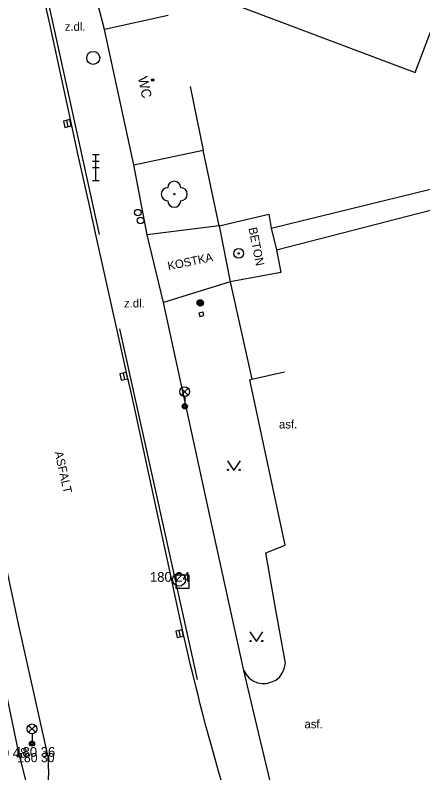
# Model space of a CAD drawing. Extents: x -538441 to -536770, y -1181008 to -1179809.
# Drawn here: x -537773.6 to -537742.3, y -1180678.1 to -1180620 of the extents above; entities that cross this region are included whole.
import ezdxf

# ---------------------------------------------------------------- set-up
doc = ezdxf.new("R2010")
doc.units = 0
for name, color, linetype in [('Vrstva 10', 7, 'Continuous'), ('Vrstva 11', 7, 'Continuous'), ('Vrstva 21', 7, 'Continuous'), ('Vrstva 22', 7, 'Continuous'), ('Vrstva 24', 7, 'Continuous'), ('Vrstva 25', 7, 'Continuous'), ('Vrstva 26', 7, 'Continuous'), ('Vrstva 27', 7, 'Continuous'), ('Vrstva 28', 7, 'Continuous'), ('Vrstva 30', 7, 'Continuous'), ('Vrstva 33', 7, 'Continuous'), ('Vrstva 36', 7, 'Continuous'), ('Vrstva 39', 7, 'Continuous'), ('Vrstva 4', 7, 'Continuous'), ('Vrstva 40', 7, 'Continuous'), ('Vrstva 41', 7, 'Continuous'), ('Vrstva 5', 7, 'Continuous'), ('Vrstva 7', 7, 'Continuous'), ('Vrstva 8', 7, 'Continuous'), ('Vrstva 9', 7, 'Continuous')]:
    doc.layers.add(name, color=color, linetype=linetype)

msp = doc.modelspace()

# ---------------------------------------------------------------- linework, layer by layer
at = {"layer": 'Vrstva 10'}
for p, q in [((-537770.915, -1180620.685), (-537772.621, -1180613.186)), ((-537769.28, -1180628.26), (-537770.915, -1180620.685)), ((-537765.509, -1180645.218), (-537767.41, -1180636.742)), ((-537764.97, -1180647.64), (-537765.509, -1180645.218)), ((-537775.93, -1180654.62), (-537773.33, -1180666.81)), ((-537761.688, -1180662.769), (-537763.319, -1180655.202)), ((-537761.219, -1180664.93), (-537761.688, -1180662.769))]:
    msp.add_line(p, q, dxfattribs=at)
for points in [[(-537767.41, -1180636.742), (-537767.883, -1180634.623), (-537768.236, -1180633.033), (-537768.761, -1180630.647), (-537769.28, -1180628.26)], [(-537763.319, -1180655.202), (-537763.728, -1180653.311), (-537764.346, -1180650.475), (-537764.657, -1180649.057), (-537764.97, -1180647.64)], [(-537758.935, -1180674.513), (-537759.17, -1180673.628), (-537759.372, -1180672.853), (-537759.546, -1180672.174), (-537759.696, -1180671.579), (-537759.953, -1180670.538), (-537760.141, -1180669.755), (-537760.28, -1180669.167), (-537760.483, -1180668.284), (-537760.68, -1180667.4), (-537761.219, -1180664.93)], [(-537773.33, -1180666.81), (-537772.713, -1180669.563)], [(-537772.713, -1180669.563), (-537771.07, -1180676.89)], [(-537756.199, -1180683.987), (-537756.511, -1180682.957), (-537756.801, -1180681.991), (-537757.071, -1180681.086), (-537757.322, -1180680.236), (-537757.554, -1180679.439), (-537757.771, -1180678.692), (-537757.972, -1180677.991), (-537758.343, -1180676.675), (-537758.662, -1180675.522), (-537758.935, -1180674.513)], [(-537771.07, -1180676.89), (-537771.02, -1180678.163), (-537771.13, -1180679.42), (-537771.4, -1180680.668), (-537771.823, -1180681.866), (-537771.94, -1180682.13)]]:
    msp.add_lwpolyline(points, dxfattribs=at)
at = {"layer": 'Vrstva 11'}
for p, q in [((-537757.908, -1180618.739), (-537742.89, -1180624.41)), ((-537742.89, -1180624.41), (-537740.772, -1180618.801)), ((-537763.452, -1180636.853), (-537764.47, -1180631.49)), ((-537753.53, -1180638.01), (-537734.2, -1180633.02)), ((-537757.93, -1180636.17), (-537754.12, -1180635.28)), ((-537754.12, -1180635.28), (-537753.93, -1180636.35)), ((-537757.93, -1180636.17), (-537763.452, -1180636.853)), ((-537753.93, -1180636.35), (-537753.53, -1180638.01)), ((-537762.187, -1180642.047), (-537763.452, -1180636.853)), ((-537753.53, -1180638.01), (-537753.2, -1180639.76)), ((-537753.2, -1180639.76), (-537757.07, -1180640.46)), ((-537757.07, -1180640.46), (-537762.187, -1180642.047)), ((-537758.607, -1180658.503), (-537762.187, -1180642.047)), ((-537755.574, -1180647.981), (-537755.408, -1180647.932)), ((-537752.87, -1180660.656), (-537755.574, -1180647.981)), ((-537756.028, -1180670.259), (-537758.607, -1180658.503)), ((-537754.35, -1180661.261), (-537752.87, -1180660.656)), ((-537773.21, -1180676.96), (-537774.66, -1180670.06)), ((-537754.899, -1180675.016), (-537756.028, -1180670.259)), ((-537753.677, -1180680.146), (-537754.899, -1180675.016)), ((-537773.21, -1180676.96), (-537771.94, -1180682.13))]:
    msp.add_line(p, q, dxfattribs=at)
for points in [[(-537766.73, -1180621.12), (-537767.266, -1180619.04), (-537767.504, -1180617.426), (-537768.734, -1180617.736), (-537769.132, -1180616.088), (-537767.464, -1180615.743)], [(-537753.93, -1180636.35), (-537735.558, -1180631.868)], [(-537752.846, -1180669.719), (-537753.593, -1180665.498), (-537754.35, -1180661.261)], [(-537756.028, -1180670.259), (-537755.852, -1180670.577), (-537755.611, -1180670.849), (-537755.316, -1180671.062), (-537754.982, -1180671.205), (-537754.625, -1180671.273), (-537754.262, -1180671.26), (-537753.95, -1180671.16), (-537753.587, -1180671.003), (-537753.307, -1180670.771), (-537753.085, -1180670.483), (-537752.931, -1180670.154), (-537752.853, -1180669.799), (-537752.846, -1180669.719)]]:
    msp.add_lwpolyline(points, dxfattribs=at)
at = {"layer": 'Vrstva 21'}
for radius in [0.375, 0.05]:
    msp.add_circle((-537756.42, -1180638.29), radius, dxfattribs=at)
at = {"layer": 'Vrstva 22'}
msp.add_circle((-537761.37, -1180633.75), 0.05, dxfattribs=at)
for centre, start, end in [((-537761.37, -1180633.25), 0, 180), ((-537761.87, -1180633.75), 90, 270), ((-537760.87, -1180633.75), 270, 90), ((-537761.37, -1180634.25), 180, 0)]:
    msp.add_arc(centre, 0.5, start, end, dxfattribs=at)
at = {"layer": 'Vrstva 24'}
for p, q in [((-537759.473, -1180642.845), (-537759.18, -1180642.78)), ((-537759.473, -1180642.845), (-537759.413, -1180643.115)), ((-537759.18, -1180642.78), (-537759.12, -1180643.05)), ((-537759.413, -1180643.115), (-537759.12, -1180643.05))]:
    msp.add_line(p, q, dxfattribs=at)
at = {"layer": 'Vrstva 25'}
for radius in [0.25, 0.2, 0.15, 0.1, 0.05]:
    msp.add_circle((-537759.37, -1180642.09), radius, dxfattribs=at)
at = {"layer": 'Vrstva 26'}
msp.add_lwpolyline([(-537761.238, -1180663.97), (-537760.238, -1180663.97), (-537760.238, -1180662.97), (-537761.238, -1180662.97)], close=True, dxfattribs=at)
at = {"layer": 'Vrstva 27'}
for p, q in [((-537769.631, -1180628.085), (-537769.523, -1180628.573)), ((-537765.295, -1180647.47), (-537765.187, -1180647.958)), ((-537761.017, -1180667.211), (-537760.909, -1180667.699))]:
    msp.add_line(p, q, dxfattribs=at)
for points in [[(-537769.875, -1180628.139), (-537769.767, -1180628.627), (-537769.279, -1180628.519), (-537769.387, -1180628.031)], [(-537765.539, -1180647.524), (-537765.431, -1180648.012), (-537764.943, -1180647.904), (-537765.051, -1180647.416)], [(-537761.261, -1180667.265), (-537761.153, -1180667.753), (-537760.665, -1180667.645), (-537760.773, -1180667.157)]]:
    msp.add_lwpolyline(points, close=True, dxfattribs=at)
msp.add_circle((-537767.589, -1180623.297), 0.5, dxfattribs=at)
at = {"layer": 'Vrstva 28'}
for centre in [(-537764.159, -1180635.161), (-537763.966, -1180635.761)]:
    msp.add_circle(centre, 0.25, dxfattribs=at)
at = {"layer": 'Vrstva 30'}
msp.add_circle((-537761.005, -1180663.307), 0.5, dxfattribs=at)
at = {"layer": 'Vrstva 33'}
for p, q in [((-537767.634, -1180630.71), (-537767.134, -1180630.71)), ((-537767.634, -1180631.21), (-537767.134, -1180631.21)), ((-537767.384, -1180632.71), (-537767.384, -1180630.71)), ((-537767.634, -1180631.71), (-537767.134, -1180631.71)), ((-537767.634, -1180632.71), (-537767.134, -1180632.71)), ((-537760.83, -1180649.153), (-537760.3, -1180648.623)), ((-537760.83, -1180648.623), (-537760.3, -1180649.153)), ((-537760.565, -1180649.263), (-537760.565, -1180650.013)), ((-537772.545, -1180675.01), (-537772.015, -1180674.48)), ((-537772.545, -1180674.48), (-537772.015, -1180675.01)), ((-537772.28, -1180675.12), (-537772.28, -1180675.87))]:
    msp.add_line(p, q, dxfattribs=at)
for centre, radius in [((-537760.565, -1180648.888), 0.375), ((-537760.565, -1180650.013), 0.2), ((-537760.565, -1180650.013), 0.145), ((-537760.565, -1180650.013), 0.0876), ((-537772.28, -1180674.745), 0.375), ((-537772.28, -1180675.87), 0.2), ((-537772.28, -1180675.87), 0.145), ((-537772.28, -1180675.87), 0.0876)]:
    msp.add_circle(centre, radius, dxfattribs=at)
at = {"layer": 'Vrstva 36'}
for points in [[(-537757.297, -1180654.182), (-537756.797, -1180654.932), (-537756.297, -1180654.182)], [(-537755.568, -1180667.309), (-537755.068, -1180668.059), (-537754.568, -1180667.309)]]:
    msp.add_lwpolyline(points, dxfattribs=at)
for centre in [(-537757.247, -1180654.882), (-537756.348, -1180654.882), (-537755.518, -1180668.009), (-537754.619, -1180668.009)]:
    msp.add_circle(centre, 0.05, dxfattribs=at)
at = {"layer": 'Vrstva 39'}
for radius in [0.09, 0.0398]:
    msp.add_circle((-537763.025, -1180624.983), radius, dxfattribs=at)
at = {"layer": 'Vrstva 5'}
for p, q in [((-537761.845, -1180620.055), (-537766.73, -1180621.12)), ((-537764.47, -1180631.49), (-537766.73, -1180621.12)), ((-537760.159, -1180625.485), (-537759.14, -1180630.38)), ((-537764.47, -1180631.49), (-537759.14, -1180630.38)), ((-537757.07, -1180640.46), (-537755.408, -1180647.932)), ((-537755.408, -1180647.932), (-537752.91, -1180647.376))]:
    msp.add_line(p, q, dxfattribs=at)
at = {"layer": 'Vrstva 7'}
msp.add_line((-537757.93, -1180636.17), (-537759.14, -1180630.38), dxfattribs=at)
at = {"layer": 'Vrstva 8'}
msp.add_line((-537757.93, -1180636.17), (-537757.07, -1180640.46), dxfattribs=at)
at = {"layer": 'Vrstva 9'}
for p, q in [((-537771.423, -1180617.261), (-537767.127, -1180636.85)), ((-537765.57, -1180644.067), (-537762.857, -1180656.29)), ((-537762.857, -1180656.29), (-537759.614, -1180670.961))]:
    msp.add_line(p, q, dxfattribs=at)

# ---------------------------------------------------------------- texts
at = {"layer": 'Vrstva 4'}
for s, height, p in [('180 24 ', 0.75, (-537763.238, -1180663.47)), ('180 48 ', 0.75, (-537775.71, -1180676.96)), ('180 36 ', 0.75, (-537773.57, -1180676.89)), ('180 30 ', 0.7, (-537773.423, -1180677.3))]:
    msp.add_text(s, height=height, dxfattribs=at).set_placement(p)
at = {"layer": 'Vrstva 40'}
for s, p in [('z.dl.', (-537769.772, -1180621.221)), ('z.dl.', (-537765.225, -1180642.437)), ('asf.', (-537753.335, -1180651.713)), ('asf.', (-537751.378, -1180674.701))]:
    msp.add_text(s, height=0.65, dxfattribs=at).set_placement(p)
for s, rotation, p in [('BETON', 281.33561, (-537755.676, -1180636.358)), ('KOSTKA', 11.764, (-537761.81, -1180639.591)), ('ASFALT', 282.85992, (-537770.562, -1180653.534))]:
    msp.add_text(s, height=0.65, rotation=rotation, dxfattribs=at).set_placement(p)
at = {"layer": 'Vrstva 41'}
msp.add_text('WC', height=0.75, rotation=282.29459, dxfattribs=at).set_placement((-537764.169, -1180624.819))

doc.saveas('drawing.dxf')
